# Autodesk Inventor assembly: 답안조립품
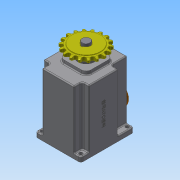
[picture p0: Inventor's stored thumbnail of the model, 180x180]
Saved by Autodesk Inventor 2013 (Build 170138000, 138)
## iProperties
Created: 2017-12
Part Number: 답안조립품
Document SubType Name: Assembly
Designer: Administrator
Mass: 2734.99 g
Surface Area: 2015.58 cm^2
Volume: 734.133 cm^3
Density: 3.72547 g/cm^3
Author: Administrator
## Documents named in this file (17)
- C:\Users\Administrator\Desktop\371208V1025\371208V1025\답안조립품.iam
- C:\Users\Administrator\Desktop\371208V1025\371208V1025\본체.ipt
- C:\Users\Administrator\Desktop\371208V1025\371208V1025\가변스프링.ipt
- C:\Users\Administrator\Desktop\371208V1025\371208V1025\멈춤나사 M3x8.ipt
- C:\Users\Administrator\Desktop\371208V1025\371208V1025\메인축.ipt
- C:\Users\Administrator\Desktop\371208V1025\371208V1025\베어링 608.ipt
- C:\Users\Administrator\Desktop\371208V1025\371208V1025\베어링 6003.ipt
- C:\Users\Administrator\Desktop\371208V1025\371208V1025\볼트 M4 x 10.ipt
- C:\Users\Administrator\Desktop\371208V1025\371208V1025\부시.ipt
- C:\Users\Administrator\Desktop\371208V1025\371208V1025\상부 캡.ipt
- C:\Users\Administrator\Desktop\371208V1025\371208V1025\서브축.ipt
- C:\Users\Administrator\Desktop\371208V1025\371208V1025\스프로킷.ipt
- C:\Users\Administrator\Desktop\371208V1025\371208V1025\슬라이더.ipt
- C:\Users\Administrator\Desktop\371208V1025\371208V1025\오일 실 8 22 7.ipt
- C:\Users\Administrator\Desktop\371208V1025\371208V1025\오일 실 17 32 8.ipt
- C:\Users\Administrator\Desktop\371208V1025\371208V1025\커버.ipt
- C:\Users\Administrator\Desktop\371208V1025\371208V1025\키 5 x 5 x 18.ipt
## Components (1 placed, 1 different names)
1. 가변스프링:1
